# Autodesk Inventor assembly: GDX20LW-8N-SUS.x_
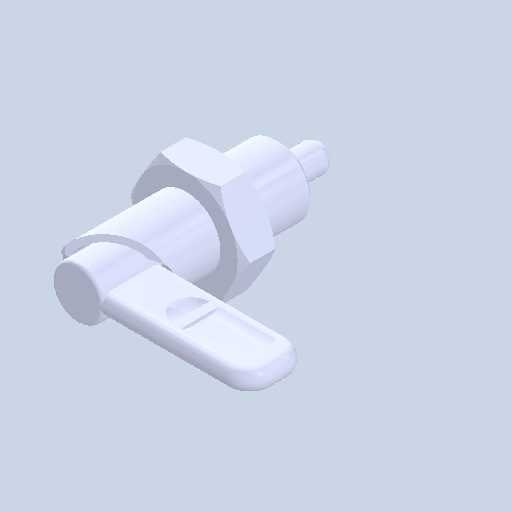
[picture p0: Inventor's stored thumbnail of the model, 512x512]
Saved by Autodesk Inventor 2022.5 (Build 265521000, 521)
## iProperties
Created: 2024-06
Part Number: GDX20LW-8N-SUS.x_
Document SubType Name: Assembly
Designer: ImaoCorp
Author: ImaoCorp
Sending System: SOLIDWORKS 2022-2022290
MC: AMD64
MC_MODEL: Intel64 Family 6 Model 60 Stepping 3, GenuineIntel
OS: Windows_NT
FRU: Parasolid Version 33.1, build 260,  4-25-2022
FORMAT: text
GUISE: transmit
KEY: FILEGDX20LW-8N-SUS.x_t
DATE: Wed Jun 12 09:33:12 2024
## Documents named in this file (4)
- Y:\5.更新分\2024年対応\xxxx_GDX\データ_imao品番\gdx20lw-8n-sus\GDX20LW-8N-SUS.x_.iam
- Y:\5.更新分\2024年対応\xxxx_GDX\データ_imao品番\gdx20lw-8n-sus\GDX20LW-8N-SUS_01.ipt
- Y:\5.更新分\2024年対応\xxxx_GDX\データ_imao品番\gdx20lw-8n-sus\GDX20LW-8N-SUS_02.ipt
- Y:\5.更新分\2024年対応\xxxx_GDX\データ_imao品番\gdx20lw-8n-sus\GDX20LW-8N-SUS_03.ipt
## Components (3 placed, 3 different names)
1. GDX20LW-8N-SUS_01
2. GDX20LW-8N-SUS_02
3. GDX20LW-8N-SUS_03
